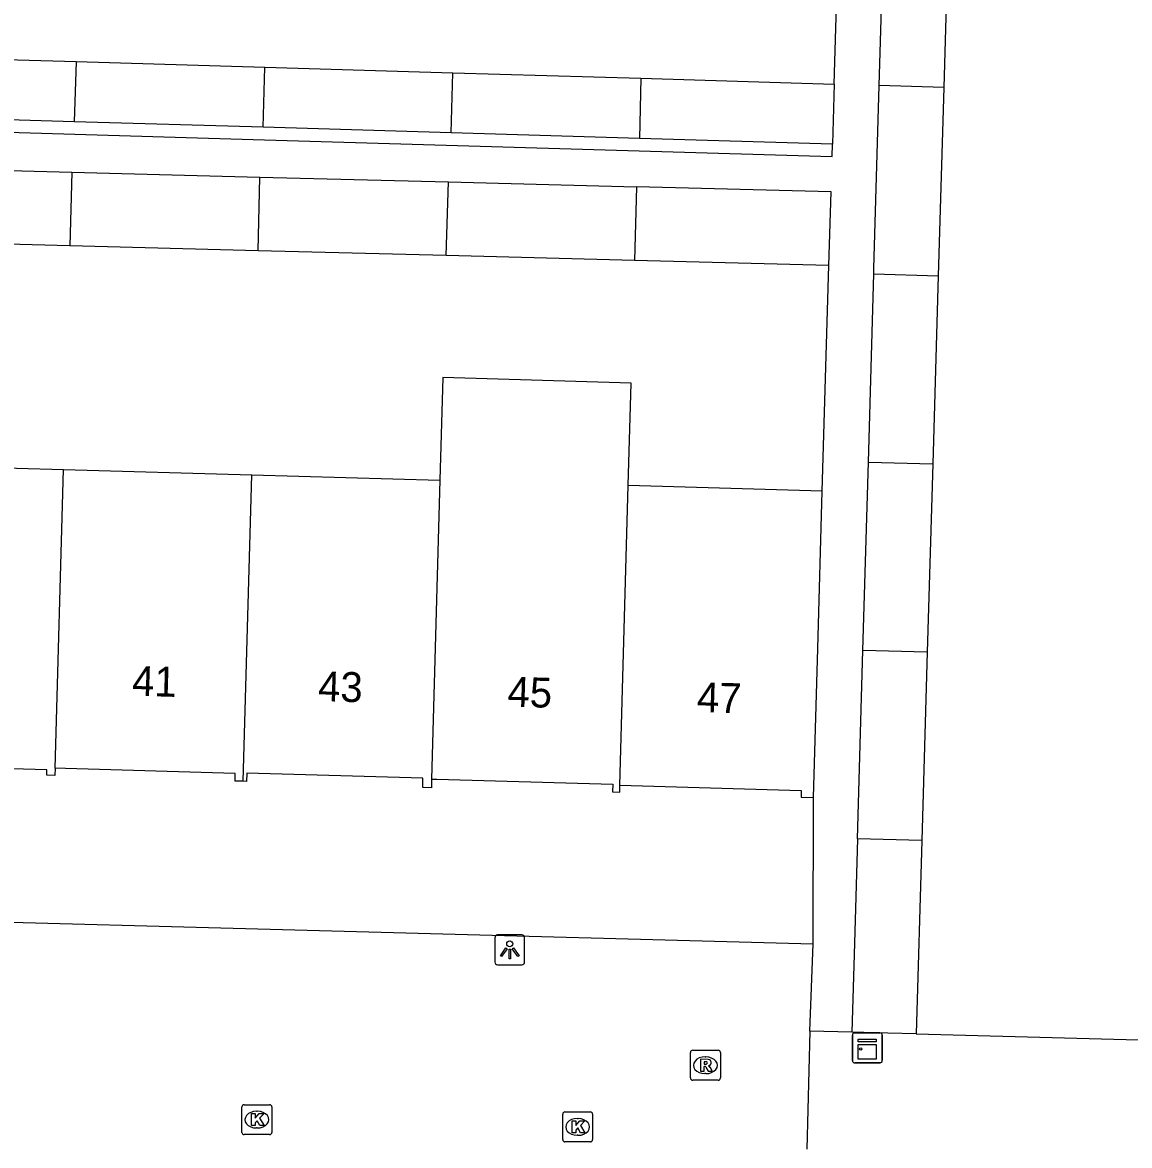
# Model space of a CAD drawing. Extents: x 162082 to 163393, y 388091 to 388632.
# Drawn here: x 162471.05 to 162508.08, y 388400.56 to 388438.13 of the extents above; entities that cross this region are included whole.
import ezdxf

# ---------------------------------------------------------------- set-up
doc = ezdxf.new("R2010")
doc.units = 0
for name, color, linetype in [('IMGEO_Kast', 7, 'Continuous'), ('IMGEO_Kolk', 7, 'Continuous'), ('IMGEO_Lichtpunt', 7, 'Continuous'), ('IMGEO_Pand', 7, 'Continuous'), ('IMGEO_Pand_nummerreeks', 7, 'Continuous'), ('IMGEO_Rijbaan_lokaal_open', 7, 'Continuous'), ('IMGEO_Rioolput', 7, 'Continuous'), ('IMGEO_Voetpad_open', 7, 'Continuous')]:
    doc.layers.add(name, color=color, linetype=linetype)

msp = doc.modelspace()

# ---------------------------------------------------------------- linework, layer by layer
at = {"layer": 'IMGEO_Kast'}
for p, q in [((162498.81, 388403.397), (162498.81, 388404.238)), ((162498.81, 388404.238), (162498.81, 388403.397)), ((162498.885, 388404.322), (162499.726, 388404.322)), ((162499.726, 388404.322), (162498.885, 388404.322)), ((162499.81, 388404.247), (162499.81, 388403.406)), ((162499.81, 388403.406), (162499.81, 388404.247)), ((162499.735, 388403.322), (162498.894, 388403.322)), ((162498.894, 388403.322), (162499.735, 388403.322))]:
    msp.add_line(p, q, dxfattribs=at)
for points in [[(162499.005, 388404.112), (162499.605, 388404.112), (162499.605, 388404.027), (162499.005, 388404.027), (162499.005, 388404.112)], [(162499.005, 388403.937), (162499.605, 388403.937), (162499.605, 388403.448), (162499.005, 388403.448), (162499.005, 388403.937)]]:
    msp.add_lwpolyline(points, dxfattribs=at)
msp.add_circle((162499.089, 388403.786), 0.0377, dxfattribs=at)
for centre, start, end in [((162498.888, 388404.244), 92.4484, 184.2845), ((162498.888, 388404.244), 92.4484, 184.2845), ((162499.732, 388404.244), 2.4484, 94.2845), ((162499.732, 388404.244), 2.4484, 94.2845), ((162498.888, 388403.4), 182.4484, 274.2845), ((162498.888, 388403.4), 182.4484, 274.2845), ((162499.732, 388403.4), 272.4484, 4.2845), ((162499.732, 388403.4), 272.4484, 4.2845)]:
    msp.add_arc(centre, 0.0779, start, end, dxfattribs=at)
at = {"layer": 'IMGEO_Kolk'}
for p, q in [((162478.389, 388400.996), (162478.389, 388401.848)), ((162478.464, 388401.922), (162479.316, 388401.922)), ((162478.877, 388401.702), (162478.902, 388401.702)), ((162479.39, 388401.848), (162479.39, 388400.996)), ((162489.119, 388400.752), (162489.119, 388401.604)), ((162489.194, 388401.678), (162490.046, 388401.678)), ((162490.12, 388401.604), (162490.12, 388400.752)), ((162489.607, 388401.458), (162489.632, 388401.458)), ((162479.316, 388400.922), (162478.464, 388400.922)), ((162478.9, 388401.142), (162478.875, 388401.142)), ((162489.63, 388400.898), (162489.605, 388400.898)), ((162490.046, 388400.678), (162489.194, 388400.678))]:
    msp.add_line(p, q, dxfattribs=at)
for points in [[(162478.389, 388400.996), (162478.389, 388401.848)], [(162478.464, 388401.922), (162479.316, 388401.922)], [(162478.71, 388401.622), (162478.833, 388401.622), (162478.833, 388401.471), (162478.963, 388401.622), (162479.127, 388401.622), (162478.981, 388401.471), (162479.134, 388401.222), (162478.982, 388401.222), (162478.897, 388401.386), (162478.833, 388401.319), (162478.833, 388401.222), (162478.71, 388401.222), (162478.71, 388401.622)], [(162479.39, 388401.848), (162479.39, 388400.996)], [(162489.119, 388400.752), (162489.119, 388401.604)], [(162489.194, 388401.678), (162490.046, 388401.678)], [(162490.12, 388401.604), (162490.12, 388400.752)], [(162489.44, 388401.378), (162489.563, 388401.378), (162489.563, 388401.227), (162489.693, 388401.378), (162489.857, 388401.378), (162489.711, 388401.227), (162489.864, 388400.978), (162489.712, 388400.978), (162489.627, 388401.142), (162489.563, 388401.075), (162489.563, 388400.978), (162489.44, 388400.978), (162489.44, 388401.378)], [(162479.316, 388400.922), (162478.464, 388400.922)], [(162490.046, 388400.678), (162489.194, 388400.678)]]:
    msp.add_lwpolyline(points, dxfattribs=at)
for centre, start, end in [((162478.466, 388401.846), 91.552, 178.448), ((162478.466, 388401.846), 91.552, 178.448), ((162479.314, 388401.846), 1.552, 88.448), ((162479.314, 388401.846), 1.552, 88.448), ((162489.196, 388401.602), 91.552, 178.448), ((162489.196, 388401.602), 91.552, 178.448), ((162490.044, 388401.602), 1.552, 88.448), ((162490.044, 388401.602), 1.552, 88.448), ((162478.466, 388400.998), 181.552, 268.448), ((162478.466, 388400.998), 181.552, 268.448), ((162479.314, 388400.998), 271.552, 358.448), ((162479.314, 388400.998), 271.552, 358.448), ((162489.196, 388400.754), 181.552, 268.448), ((162489.196, 388400.754), 181.552, 268.448), ((162490.044, 388400.754), 271.552, 358.448), ((162490.044, 388400.754), 271.552, 358.448)]:
    msp.add_arc(centre, 0.0765, start, end, dxfattribs=at)
for centre, major_axis, ratio, start_param, end_param in [((162478.876, 388401.422), (-0.387, 0.002), 0.722429, 4.712389, 7.853982), ((162478.901, 388401.422), (-0.39, 0.002), 0.717154, 1.570796, 4.712389), ((162489.606, 388401.178), (-0.387, 0.002), 0.722429, 4.712389, 7.853982), ((162489.631, 388401.178), (-0.39, 0.002), 0.717154, 1.570796, 4.712389)]:
    msp.add_ellipse(centre, major_axis=major_axis, ratio=ratio, start_param=start_param, end_param=end_param, dxfattribs=at)
at = {"layer": 'IMGEO_Lichtpunt'}
for p, q in [((162487.75, 388407.6), (162486.942, 388407.6)), ((162487.75, 388407.6), (162486.942, 388407.6)), ((162486.848, 388407.505), (162486.848, 388406.698)), ((162486.848, 388407.505), (162486.848, 388406.698)), ((162487.844, 388406.698), (162487.844, 388407.505)), ((162487.844, 388406.698), (162487.844, 388407.505)), ((162486.942, 388406.604), (162487.75, 388406.604)), ((162486.942, 388406.604), (162487.75, 388406.604))]:
    msp.add_line(p, q, dxfattribs=at)
for points in [[(162487.222, 388407.169), (162487.261, 388407.141), (162487.073, 388406.879), (162487.035, 388406.906), (162487.222, 388407.169)], [(162487.324, 388407.121), (162487.371, 388407.121), (162487.371, 388406.799), (162487.324, 388406.799), (162487.324, 388407.121)], [(162487.434, 388407.141), (162487.472, 388407.168), (162487.659, 388406.906), (162487.62, 388406.878), (162487.434, 388407.141)]]:
    msp.add_lwpolyline(points, dxfattribs=at)
msp.add_circle((162487.347, 388407.303), 0.0994, dxfattribs=at)
for centre, start, end in [((162486.942, 388407.505), 90, 180), ((162486.942, 388407.505), 90, 180), ((162487.75, 388407.505), 0, 90), ((162487.75, 388407.505), 0, 90), ((162486.942, 388406.698), 180, 270), ((162486.942, 388406.698), 180, 270), ((162487.75, 388406.698), 270, 0), ((162487.75, 388406.698), 270, 360)]:
    msp.add_arc(centre, 0.0946, start, end, dxfattribs=at)
at = {"layer": 'IMGEO_Pand'}
for points in [[(162499.711, 388436.012), (162499.894, 388442.31)], [(162502.048, 388442.25), (162501.864, 388435.951)], [(162466.557, 388436.999), (162472.838, 388436.814)], [(162472.838, 388436.814), (162472.78, 388434.805)], [(162472.838, 388436.814), (162479.152, 388436.628)], [(162479.098, 388434.619), (162479.152, 388436.628)], [(162479.152, 388436.628), (162485.448, 388436.442)], [(162485.393, 388434.433), (162485.448, 388436.442)], [(162485.448, 388436.442), (162491.738, 388436.257)], [(162491.738, 388436.257), (162491.683, 388434.248)], [(162491.738, 388436.257), (162498.205, 388436.066)], [(162498.205, 388436.066), (162498.145, 388434.057)], [(162499.528, 388429.715), (162499.533, 388429.895), (162499.711, 388436.012)], [(162501.864, 388435.951), (162499.711, 388436.012)], [(162501.864, 388435.951), (162501.681, 388429.655)], [(162472.78, 388434.805), (162466.503, 388434.99)], [(162479.098, 388434.619), (162472.78, 388434.805)], [(162485.393, 388434.433), (162479.098, 388434.619)], [(162491.683, 388434.248), (162485.393, 388434.433)], [(162498.145, 388434.057), (162491.683, 388434.248)], [(162466.402, 388433.282), (162472.699, 388433.118)], [(162472.699, 388433.118), (162472.629, 388430.655)], [(162472.699, 388433.118), (162478.983, 388432.954)], [(162478.928, 388430.491), (162478.983, 388432.954)], [(162478.983, 388432.954), (162485.294, 388432.789)], [(162485.225, 388430.327), (162485.294, 388432.789)], [(162485.294, 388432.789), (162491.591, 388432.625)], [(162491.591, 388432.625), (162491.522, 388430.163)], [(162498.026, 388429.993), (162498.098, 388432.455), (162491.591, 388432.625)], [(162472.629, 388430.655), (162466.332, 388430.819)], [(162478.928, 388430.491), (162472.629, 388430.655)], [(162485.225, 388430.327), (162478.928, 388430.491)], [(162491.522, 388430.163), (162485.225, 388430.327)], [(162498.026, 388429.993), (162491.522, 388430.163)], [(162499.345, 388423.416), (162499.528, 388429.715)], [(162499.528, 388429.715), (162501.681, 388429.655)], [(162501.681, 388429.655), (162501.498, 388423.356)], [(162491.312, 388422.63), (162491.408, 388426.064), (162485.111, 388426.243), (162485.014, 388422.809)], [(162499.162, 388417.117), (162499.345, 388423.416)], [(162499.345, 388423.416), (162501.498, 388423.356)], [(162466.122, 388423.345), (162472.419, 388423.166)], [(162472.138, 388413.174), (162472.419, 388423.166)], [(162472.419, 388423.166), (162478.717, 388422.987)], [(162478.429, 388412.741), (162478.717, 388422.987)], [(162478.717, 388422.987), (162485.014, 388422.809)], [(162501.498, 388423.356), (162501.314, 388417.057)], [(162485.014, 388422.809), (162484.733, 388412.817)], [(162491.032, 388412.608), (162491.312, 388422.63)], [(162497.803, 388422.446), (162491.312, 388422.63)], [(162497.512, 388412.193), (162497.654, 388417.188), (162497.803, 388422.446)], [(162498.979, 388410.821), (162499.162, 388417.117)], [(162501.314, 388417.057), (162499.162, 388417.117)], [(162501.314, 388417.057), (162501.131, 388410.76)], [(162472.138, 388413.174), (162472.131, 388412.933), (162471.862, 388412.941), (162471.867, 388413.121), (162465.979, 388413.288), (162465.84, 388413.292)], [(162478.429, 388412.741), (162478.159, 388412.748), (162478.166, 388413.003), (162472.481, 388413.164), (162472.138, 388413.174)], [(162484.733, 388412.817), (162484.725, 388412.522), (162484.436, 388412.53), (162484.445, 388412.841), (162478.547, 388413.008), (162478.539, 388412.738), (162478.429, 388412.741)], [(162484.733, 388412.817), (162484.8, 388412.815), (162484.906, 388412.812), (162490.793, 388412.646), (162490.785, 388412.385), (162491.026, 388412.378), (162491.032, 388412.608)], [(162491.032, 388412.608), (162497.101, 388412.436), (162497.094, 388412.205), (162497.512, 388412.193)], [(162498.979, 388410.821), (162498.877, 388407.326), (162498.791, 388404.353)], [(162501.131, 388410.76), (162498.979, 388410.821)], [(162501.131, 388410.76), (162500.943, 388404.291)], [(162500.943, 388404.291), (162500, 388404.319), (162498.791, 388404.353)]]:
    msp.add_lwpolyline(points, dxfattribs=at)
at = {"layer": 'IMGEO_Rijbaan_lokaal_open'}
for points in [[(162466.108, 388408.15), (162497.499, 388407.298)], [(162497.388, 388404.385), (162497.499, 388407.298)], [(162497.388, 388404.385), (162497.281, 388400.433)]]:
    msp.add_lwpolyline(points, dxfattribs=at)
at = {"layer": 'IMGEO_Rioolput'}
for p, q in [((162493.393, 388402.815), (162493.393, 388403.667)), ((162493.468, 388403.741), (162494.32, 388403.741)), ((162493.881, 388403.521), (162493.906, 388403.521)), ((162494.394, 388403.667), (162494.394, 388402.815)), ((162494.32, 388402.741), (162493.468, 388402.741)), ((162493.904, 388402.961), (162493.879, 388402.961))]:
    msp.add_line(p, q, dxfattribs=at)
for points in [[(162493.393, 388402.815), (162493.393, 388403.667)], [(162493.468, 388403.741), (162494.32, 388403.741)], [(162494.394, 388403.667), (162494.394, 388402.815)], [(162493.982, 388403.439), (162493.73, 388403.441), (162493.73, 388403.041)], [(162493.73, 388403.041), (162493.854, 388403.041), (162493.854, 388403.203), (162493.865, 388403.203)], [(162493.908, 388403.36), (162493.854, 388403.36), (162493.854, 388403.279)], [(162493.854, 388403.279), (162493.906, 388403.279)], [(162493.912, 388403.174), (162493.983, 388403.041), (162494.123, 388403.041), (162494.058, 388403.167)], [(162494.32, 388402.741), (162493.468, 388402.741)]]:
    msp.add_lwpolyline(points, dxfattribs=at)
for centre, radius, start, end in [((162493.47, 388403.665), 0.0765, 91.552, 178.448), ((162493.47, 388403.665), 0.0765, 91.552, 178.448), ((162494.318, 388403.665), 0.0765, 1.552, 88.448), ((162494.318, 388403.665), 0.0765, 1.552, 88.448), ((162493.864, 388403.15), 0.0533, 26.0293, 88.6989), ((162493.89, 388403.468), 0.19, 274.7715, 282.9687), ((162493.914, 388403.264), 0.0964, 77.0061, 93.1865), ((162493.928, 388403.321), 0.0378, 276.6634, 79.6772), ((162493.981, 388403.329), 0.109, 350.3612, 89.416), ((162493.979, 388403.329), 0.112, 277.5842, 350.9817), ((162493.963, 388403.114), 0.108, 29.5134, 73.7905), ((162493.47, 388402.817), 0.0765, 181.552, 268.448), ((162493.47, 388402.817), 0.0765, 181.552, 268.448), ((162494.318, 388402.817), 0.0765, 271.552, 358.448), ((162494.318, 388402.817), 0.0765, 271.552, 358.448)]:
    msp.add_arc(centre, radius, start, end, dxfattribs=at)
for centre, major_axis, ratio, start_param, end_param in [((162493.88, 388403.241), (-0.387, 0.002), 0.722429, 4.712389, 7.853982), ((162493.905, 388403.241), (-0.39, 0.002), 0.717154, 1.570796, 4.712389)]:
    msp.add_ellipse(centre, major_axis=major_axis, ratio=ratio, start_param=start_param, end_param=end_param, dxfattribs=at)
at = {"layer": 'IMGEO_Voetpad_open'}
for points in [[(162498.205, 388436.066), (162498.518, 388446.563)], [(162434.808, 388435.925), (162434.796, 388435.51), (162438.558, 388435.399), (162451.799, 388435.008), (162463.467, 388434.663), (162478.763, 388434.212), (162498.133, 388433.64), (162498.145, 388434.057)], [(162497.803, 388422.446), (162498.026, 388429.993)], [(162497.499, 388407.298), (162497.512, 388412.193)], [(162498.791, 388404.353), (162497.388, 388404.385)], [(162500.943, 388404.291), (162511.285, 388404.011)]]:
    msp.add_lwpolyline(points, dxfattribs=at)

# ---------------------------------------------------------------- texts
at = {"layer": 'IMGEO_Pand_nummerreeks'}
for s, p in [('41', (162474.705, 388415.605)), ('43', (162480.927, 388415.425)), ('45', (162487.263, 388415.241)), ('47', (162493.599, 388415.058))]:
    msp.add_text(s, height=1, rotation=358.3442, dxfattribs=at).set_placement(p)

doc.saveas('drawing.dxf')
